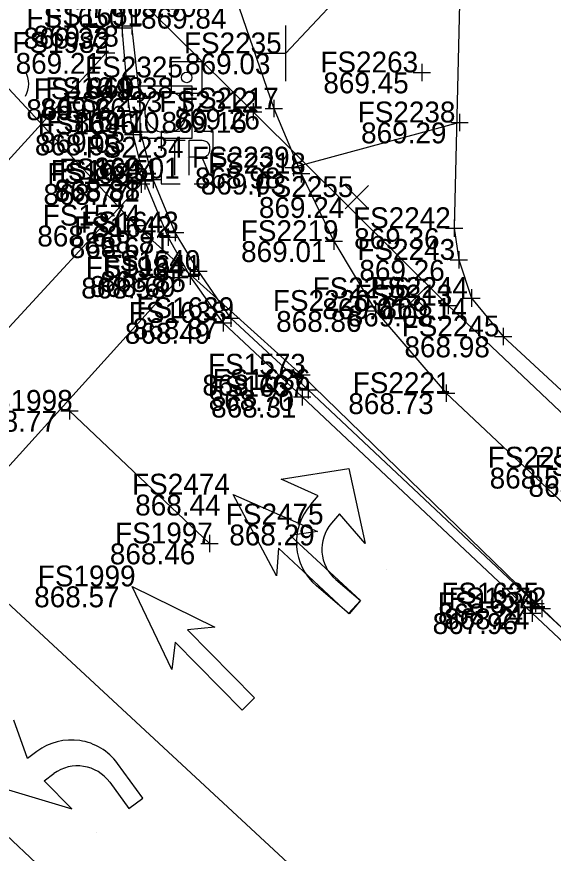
# Model space of a CAD drawing. Extents: x 1479420 to 1479833, y 379731 to 380103.
# Drawn here: x 1479689.07 to 1479719.92, y 379864.1 to 379912.16 of the extents above; entities that cross this region are included whole.
import ezdxf

# ---------------------------------------------------------------- set-up
doc = ezdxf.new("R2010")
doc.units = 0
for name, color, linetype in [('Default', 7, 'Continuous'), ('PM_X_Cells', 7, 'Continuous'), ('PM_X_Channelizing_Line', 7, 'Continuous'), ('PM_X_CL_Double_Solid', 7, 'Continuous'), ('PM_X_Crosswalk', 7, 'Continuous'), ('PM_X_Lane_Line', 7, 'Continuous'), ('PM_X_Stop_Line', 7, 'Continuous'), ('PV_X_Curb', 7, 'Continuous'), ('PV_X_Walk', 7, 'Continuous'), ('SG_X_Poles', 7, 'Continuous'), ('SG_X_PullBox', 7, 'Continuous'), ('SN_X_Public', 7, 'Continuous'), ('SV_X_Random_Point', 7, 'Continuous'), ('SV_X_Shot_Marker', 7, 'Continuous'), ('SV_X_Text_Elevation', 7, 'Continuous'), ('SV_X_Text_Name', 7, 'Continuous'), ('UT_X_Gas', 7, 'Continuous'), ('UT_X_Water', 7, 'Continuous'), ('UT_X_Water_Cells', 7, 'Continuous'), ('VG_X_Flower_Bed', 7, 'Continuous')]:
    doc.layers.add(name, color=color, linetype=linetype)

msp = doc.modelspace()

# ---------------------------------------------------------------- linework, layer by layer
at = {"layer": 'Default'}
msp.add_line((1479704.525, 379910.056), (1479711.29, 379917.236), dxfattribs=at)
at = {"layer": 'PM_X_Cells'}
for p, q in [((1479704.278, 379885.594), (1479708.173, 379886.208)), ((1479708.173, 379886.208), (1479709.112, 379881.892)), ((1479704.278, 379885.594), (1479704.278, 379885.594)), ((1479706.413, 379884.644), (1479704.278, 379885.594)), ((1479701.526, 379884.706), (1479701.526, 379884.706)), ((1479701.526, 379884.706), (1479706.374, 379882.583)), ((1479704.015, 379880.035), (1479701.526, 379884.706)), ((1479705.979, 379884.137), (1479706.413, 379884.644)), ((1479707.628, 379883.603), (1479707.17, 379883.069)), ((1479709.112, 379881.892), (1479707.628, 379883.603)), ((1479706.374, 379882.583), (1479704.801, 379882.355)), ((1479704.801, 379882.355), (1479708.836, 379878.618)), ((1479704.121, 379881.622), (1479704.015, 379880.035)), ((1479708.156, 379877.884), (1479704.121, 379881.622)), ((1479710.354, 379880.39), (1479710.354, 379880.39)), ((1479707.421, 379879.83), (1479708.836, 379878.618)), ((1479695.718, 379879.435), (1479695.718, 379879.435)), ((1479695.718, 379879.435), (1479700.468, 379877.1)), ((1479697.999, 379874.659), (1479695.718, 379879.435)), ((1479708.185, 379877.859), (1479706.303, 379879.471)), ((1479708.836, 379878.618), (1479708.156, 379877.884)), ((1479708.836, 379878.618), (1479708.185, 379877.859)), ((1479708.496, 379878.251), (1479708.496, 379878.251)), ((1479700.468, 379877.1), (1479698.886, 379876.942)), ((1479698.886, 379876.942), (1479702.753, 379873.031)), ((1479698.175, 379876.239), (1479697.999, 379874.659)), ((1479702.042, 379872.328), (1479698.175, 379876.239)), ((1479702.753, 379873.031), (1479702.042, 379872.328)), ((1479702.398, 379872.68), (1479702.398, 379872.68)), ((1479689.698, 379869.557), (1479688.914, 379871.759)), ((1479690.236, 379869.951), (1479689.698, 379869.557)), ((1479696.327, 379867.269), (1479694.864, 379869.27)), ((1479690.643, 379868.266), (1479691.21, 379868.681)), ((1479692.234, 379866.654), (1479690.643, 379868.266)), ((1479694.42, 379868.183), (1479695.52, 379866.679)), ((1479688.004, 379867.922), (1479692.234, 379866.654)), ((1479695.52, 379866.679), (1479696.327, 379867.269)), ((1479693.636, 379865.301), (1479693.636, 379865.301))]:
    msp.add_line(p, q, dxfattribs=at)
for centre, radius, start, end in [((1479708.437, 379881.963), 3.281, 138.5133, 229.4218), ((1479708.915, 379881.575), 2.297, 139.4218, 229.4218), ((1479692.215, 379867.333), 3.281, 36.1769, 127.0854), ((1479692.566, 379866.827), 2.297, 36.1769, 126.1769)]:
    msp.add_arc(centre, radius, start, end, dxfattribs=at)
at = {"layer": 'PM_X_Channelizing_Line'}
msp.add_lwpolyline([(1479685.324, 379881.456), (1479709.405, 379859.144), (1479736.1, 379834.256)], dxfattribs=at)
at = {"layer": 'PM_X_CL_Double_Solid'}
msp.add_lwpolyline([(1479794.219, 379768.772), (1479779.093, 379781.771), (1479763.159, 379795.427), (1479746.619, 379810.624), (1479732.239, 379823.873), (1479714.719, 379840.653), (1479700.713, 379853.615), (1479677.934, 379875.066)], dxfattribs=at)
at = {"layer": 'PM_X_Crosswalk'}
for p, q in [((1479656.672, 379868.951), (1479694.216, 379910.084)), ((1479661.061, 379864.454), (1479696.232, 379902.554))]:
    msp.add_line(p, q, dxfattribs=at)
at = {"layer": 'PM_X_Lane_Line'}
msp.add_line((1479700.154, 379881.903), (1479692.101, 379889.519), dxfattribs=at)
at = {"layer": 'PM_X_Stop_Line'}
msp.add_line((1479698.43, 379897.175), (1479678.605, 379875.296), dxfattribs=at)
at = {"layer": 'PV_X_Curb'}
for points in [[(1479714.573, 379931.716), (1479714.771, 379922.599), (1479714.229, 379900.013), (1479714.491, 379898.192), (1479715.218, 379896.002), (1479717.036, 379893.796), (1479731.944, 379880.013), (1479745.709, 379867.308), (1479763.187, 379850.751), (1479775.061, 379839.578), (1479781.928, 379833.121), (1479783.777, 379830.713), (1479784.214, 379828.705), (1479783.141, 379825.906)], [(1479818.811, 379784.125), (1479817.439, 379785.583), (1479804.233, 379798.167), (1479791.741, 379810.033), (1479778.638, 379821.983), (1479775.464, 379824.819), (1479758.378, 379840.845), (1479740.8, 379857.042), (1479740.592, 379857.626), (1479737.808, 379860.038), (1479735.87, 379861.852), (1479733.787, 379863.763), (1479718.701, 379877.898), (1479705.478, 379890.334), (1479700.95, 379894.575), (1479699.048, 379897.264), (1479697.778, 379899.5), (1479696.445, 379902.732), (1479695.776, 379905.397), (1479695.475, 379907.419), (1479695.142, 379911.53), (1479695.083, 379915.321)], [(1479783.191, 379825.805), (1479782.298, 379824.723), (1479781.461, 379824.102), (1479780.469, 379823.552), (1479779.204, 379823.559), (1479778.041, 379823.771), (1479776.54, 379824.685), (1479775.613, 379825.569), (1479758.651, 379841.237), (1479741.143, 379857.755), (1479738.162, 379860.576), (1479738.292, 379860.892), (1479733.926, 379864.875), (1479733.77, 379864.743), (1479718.903, 379878.446), (1479705.833, 379890.72), (1479701.383, 379894.844), (1479699.526, 379897.551), (1479698.177, 379899.762), (1479696.913, 379902.812), (1479696.188, 379905.546), (1479696.149, 379907.481), (1479695.686, 379911.644), (1479695.62, 379915.117)]]:
    msp.add_lwpolyline(points, dxfattribs=at)
at = {"layer": 'PV_X_Walk'}
msp.add_lwpolyline([(1479714.407, 379931.65), (1479709.589, 379929.394), (1479706.362, 379927.006), (1479703.827, 379924.359), (1479702.38, 379922.179), (1479701.604, 379920.676), (1479701.232, 379918.285), (1479701.216, 379916.698), (1479701.871, 379912.679), (1479703.861, 379906.887), (1479705.425, 379903.147), (1479707.313, 379899.269), (1479709.707, 379895.256), (1479713.76, 379890.533), (1479726.083, 379878.959), (1479737.973, 379867.989), (1479746.242, 379860.487), (1479749.391, 379863.573), (1479751.936, 379861.299), (1479749.037, 379858.043), (1479762.483, 379845.218), (1479775.26, 379833.23), (1479781.252, 379827.717), (1479783.036, 379825.875)], dxfattribs=at)
at = {"layer": 'SG_X_Poles'}
for points in [[(1479697.944, 379907.773), (1479699.744, 379907.773), (1479699.744, 379909.573), (1479697.944, 379909.573)], [(1479696.157, 379905.179), (1479699.157, 379905.179), (1479699.157, 379908.179), (1479696.157, 379908.179)]]:
    msp.add_lwpolyline(points, close=True, dxfattribs=at)
for centre, radius in [((1479698.844, 379908.673), 0.3), ((1479697.657, 379906.679), 1.2)]:
    msp.add_circle(centre, radius, dxfattribs=at)
at = {"layer": 'SG_X_PullBox'}
msp.add_line((1479698.871, 379904.064), (1479698.871, 379904.064), dxfattribs=at)
for points in [[(1479698.471, 379905.564), (1479697.371, 379905.564), (1479697.371, 379904.464)], [(1479700.371, 379904.464), (1479700.371, 379905.564), (1479699.271, 379905.564)], [(1479697.515, 379905.064), (1479698.759, 379905.064)], [(1479698.145, 379905.064), (1479698.145, 379903.064)], [(1479698.983, 379903.064), (1479698.983, 379905.064), (1479699.739, 379905.064), (1479699.817, 379905.048), (1479699.928, 379905.016), (1479699.975, 379904.985), (1479700.022, 379904.953), (1479700.085, 379904.874), (1479700.132, 379904.796), (1479700.164, 379904.67), (1479700.164, 379904.481), (1479700.148, 379904.418), (1479700.117, 379904.323), (1479700.054, 379904.213), (1479699.991, 379904.166), (1479699.943, 379904.134), (1479699.912, 379904.118), (1479699.865, 379904.103), (1479699.723, 379904.087), (1479698.983, 379904.087)], [(1479699.723, 379904.087), (1479700.164, 379903.064)], [(1479697.371, 379903.664), (1479697.371, 379902.564), (1479698.471, 379902.564)], [(1479699.271, 379902.564), (1479700.371, 379902.564), (1479700.371, 379903.664)]]:
    msp.add_lwpolyline(points, dxfattribs=at)
at = {"layer": 'SN_X_Public'}
for p, q in [((1479704.525, 379911.656), (1479704.525, 379908.456)), ((1479704.525, 379910.056), (1479702.925, 379910.056))]:
    msp.add_line(p, q, dxfattribs=at)
at = {"layer": 'SV_X_Random_Point'}
for p, q in [((1479707.962, 379901.133), (1479709.296, 379902.468)), ((1479707.962, 379902.468), (1479709.296, 379901.133)), ((1479711.313, 379895.319), (1479712.647, 379896.654)), ((1479711.313, 379896.654), (1479712.647, 379895.319))]:
    msp.add_line(p, q, dxfattribs=at)
at = {"layer": 'SV_X_Shot_Marker'}
for p, q in [((1479695.142, 379912.03), (1479695.142, 379911.03)), ((1479695.686, 379912.144), (1479695.686, 379911.144)), ((1479694.642, 379911.53), (1479695.642, 379911.53)), ((1479695.142, 379911.53), (1479695.142, 379911.53)), ((1479695.186, 379911.644), (1479696.186, 379911.644)), ((1479695.686, 379911.644), (1479695.686, 379911.644)), ((1479694.216, 379910.584), (1479694.216, 379909.584)), ((1479693.716, 379910.084), (1479694.716, 379910.084)), ((1479694.216, 379910.084), (1479694.216, 379910.084)), ((1479712.371, 379909.461), (1479712.371, 379908.461)), ((1479711.871, 379908.961), (1479712.871, 379908.961)), ((1479712.371, 379908.961), (1479712.371, 379908.961)), ((1479695.475, 379907.919), (1479695.475, 379906.919)), ((1479696.149, 379907.981), (1479696.149, 379906.981)), ((1479694.975, 379907.419), (1479695.975, 379907.419)), ((1479695.475, 379907.419), (1479695.475, 379907.419)), ((1479695.649, 379907.481), (1479696.649, 379907.481)), ((1479696.149, 379907.481), (1479696.149, 379907.481)), ((1479702.659, 379907.194), (1479702.659, 379906.194)), ((1479703.861, 379907.387), (1479703.861, 379906.387)), ((1479702.159, 379906.694), (1479703.159, 379906.694)), ((1479702.659, 379906.694), (1479702.659, 379906.694)), ((1479703.361, 379906.887), (1479704.361, 379906.887)), ((1479703.861, 379906.887), (1479703.861, 379906.887)), ((1479714.524, 379906.587), (1479714.524, 379905.587)), ((1479696.188, 379906.046), (1479696.188, 379905.046)), ((1479714.024, 379906.087), (1479715.024, 379906.087)), ((1479714.524, 379906.087), (1479714.524, 379906.087)), ((1479695.688, 379905.546), (1479696.688, 379905.546)), ((1479695.776, 379905.897), (1479695.776, 379904.897)), ((1479696.188, 379905.546), (1479696.188, 379905.546)), ((1479695.276, 379905.397), (1479696.276, 379905.397)), ((1479695.776, 379905.397), (1479695.776, 379905.397)), ((1479704.993, 379903.996), (1479704.993, 379902.996)), ((1479705.425, 379903.647), (1479705.425, 379902.647)), ((1479696.445, 379903.232), (1479696.445, 379902.232)), ((1479696.913, 379903.312), (1479696.913, 379902.312)), ((1479704.493, 379903.496), (1479705.493, 379903.496)), ((1479704.925, 379903.147), (1479705.925, 379903.147)), ((1479704.993, 379903.496), (1479704.993, 379903.496)), ((1479705.425, 379903.147), (1479705.425, 379903.147)), ((1479695.945, 379902.732), (1479696.945, 379902.732)), ((1479696.232, 379903.054), (1479696.232, 379902.054)), ((1479696.413, 379902.812), (1479697.413, 379902.812)), ((1479696.445, 379902.732), (1479696.445, 379902.732)), ((1479696.913, 379902.812), (1479696.913, 379902.812)), ((1479695.732, 379902.554), (1479696.732, 379902.554)), ((1479696.232, 379902.554), (1479696.232, 379902.554)), ((1479695.924, 379900.661), (1479695.924, 379899.661)), ((1479698.177, 379900.262), (1479698.177, 379899.262)), ((1479714.229, 379900.513), (1479714.229, 379899.513)), ((1479695.424, 379900.161), (1479696.424, 379900.161)), ((1479695.924, 379900.161), (1479695.924, 379900.161)), ((1479697.677, 379899.762), (1479698.677, 379899.762)), ((1479697.778, 379900), (1479697.778, 379899)), ((1479698.177, 379899.762), (1479698.177, 379899.762)), ((1479707.313, 379899.769), (1479707.313, 379898.769)), ((1479713.729, 379900.013), (1479714.729, 379900.013)), ((1479714.229, 379900.013), (1479714.229, 379900.013)), ((1479697.278, 379899.5), (1479698.278, 379899.5)), ((1479697.778, 379899.5), (1479697.778, 379899.5)), ((1479706.813, 379899.269), (1479707.813, 379899.269)), ((1479707.313, 379899.269), (1479707.313, 379899.269)), ((1479714.491, 379898.692), (1479714.491, 379897.692)), ((1479699.526, 379898.051), (1479699.526, 379897.051)), ((1479713.991, 379898.192), (1479714.991, 379898.192)), ((1479714.491, 379898.192), (1479714.491, 379898.192)), ((1479698.43, 379897.675), (1479698.43, 379896.675)), ((1479699.026, 379897.551), (1479700.026, 379897.551)), ((1479699.048, 379897.764), (1479699.048, 379896.764)), ((1479699.526, 379897.551), (1479699.526, 379897.551)), ((1479697.93, 379897.175), (1479698.93, 379897.175)), ((1479698.43, 379897.175), (1479698.43, 379897.175)), ((1479698.548, 379897.264), (1479699.548, 379897.264)), ((1479699.048, 379897.264), (1479699.048, 379897.264)), ((1479715.218, 379896.502), (1479715.218, 379895.502)), ((1479713.881, 379896.067), (1479713.881, 379895.067)), ((1479714.718, 379896.002), (1479715.718, 379896.002)), ((1479715.218, 379896.002), (1479715.218, 379896.002)), ((1479709.707, 379895.756), (1479709.707, 379894.756)), ((1479713.381, 379895.567), (1479714.381, 379895.567)), ((1479713.881, 379895.567), (1479713.881, 379895.567)), ((1479700.95, 379895.075), (1479700.95, 379894.075)), ((1479701.383, 379895.344), (1479701.383, 379894.344)), ((1479709.207, 379895.256), (1479710.207, 379895.256)), ((1479709.707, 379895.256), (1479709.707, 379895.256)), ((1479700.45, 379894.575), (1479701.45, 379894.575)), ((1479700.883, 379894.844), (1479701.883, 379894.844)), ((1479700.95, 379894.575), (1479700.95, 379894.575)), ((1479701.383, 379894.844), (1479701.383, 379894.844)), ((1479717.036, 379894.296), (1479717.036, 379893.296)), ((1479716.536, 379893.796), (1479717.536, 379893.796)), ((1479717.036, 379893.796), (1479717.036, 379893.796)), ((1479705.441, 379892.096), (1479705.441, 379891.096)), ((1479704.941, 379891.596), (1479705.941, 379891.596)), ((1479705.441, 379891.596), (1479705.441, 379891.596)), ((1479705.833, 379891.22), (1479705.833, 379890.22)), ((1479705.333, 379890.72), (1479706.333, 379890.72)), ((1479705.478, 379890.834), (1479705.478, 379889.834)), ((1479705.833, 379890.72), (1479705.833, 379890.72)), ((1479713.76, 379891.033), (1479713.76, 379890.033)), ((1479704.978, 379890.334), (1479705.978, 379890.334)), ((1479705.478, 379890.334), (1479705.478, 379890.334)), ((1479713.26, 379890.533), (1479714.26, 379890.533)), ((1479713.76, 379890.533), (1479713.76, 379890.533)), ((1479692.101, 379890.019), (1479692.101, 379889.019)), ((1479691.601, 379889.519), (1479692.601, 379889.519)), ((1479692.101, 379889.519), (1479692.101, 379889.519)), ((1479700.154, 379882.403), (1479700.154, 379881.403)), ((1479699.654, 379881.903), (1479700.654, 379881.903)), ((1479700.154, 379881.903), (1479700.154, 379881.903)), ((1479718.903, 379878.946), (1479718.903, 379877.946)), ((1479719.261, 379878.671), (1479719.261, 379877.671)), ((1479718.403, 379878.446), (1479719.403, 379878.446)), ((1479718.701, 379878.398), (1479718.701, 379877.398)), ((1479718.761, 379878.171), (1479719.761, 379878.171)), ((1479718.903, 379878.446), (1479718.903, 379878.446)), ((1479719.261, 379878.171), (1479719.261, 379878.171)), ((1479718.201, 379877.898), (1479719.201, 379877.898)), ((1479718.701, 379877.898), (1479718.701, 379877.898))]:
    msp.add_line(p, q, dxfattribs=at)
at = {"layer": 'UT_X_Gas'}
msp.add_lwpolyline([(1479667.444, 379946.572), (1479666.862, 379942.802), (1479667.538, 379940.507), (1479675.403, 379934.504), (1479682.743, 379926.326), (1479692.421, 379916.824), (1479702.659, 379906.694), (1479713.881, 379895.567), (1479724.225, 379885.781), (1479733.117, 379877.795), (1479742.697, 379869.326), (1479754.816, 379857.131), (1479762.869, 379849.318), (1479772.436, 379840.641), (1479780.346, 379832.715), (1479784.901, 379828.191), (1479795.906, 379818.324), (1479806.128, 379806.719), (1479816.671, 379794.927)], dxfattribs=at)
at = {"layer": 'UT_X_Water'}
msp.add_lwpolyline([(1479682.752, 379913.809), (1479688.353, 379908.314), (1479695.924, 379900.161), (1479705.441, 379891.596), (1479719.261, 379878.171), (1479726.79, 379870.913), (1479729.608, 379870.544), (1479735.551, 379869.684), (1479739.947, 379866.49), (1479744.65, 379861.847), (1479745.833, 379856.023), (1479753.929, 379847.124), (1479764.701, 379835.97), (1479779.815, 379822.167), (1479798.248, 379804.283), (1479815.468, 379787.444)], dxfattribs=at)
at = {"layer": 'UT_X_Water_Cells'}
msp.add_arc((1479688.366, 379908.302), 1.4, 330.0184, 29.9816, dxfattribs=at)
at = {"layer": 'VG_X_Flower_Bed'}
msp.add_line((1479714.524, 379906.087), (1479704.993, 379903.496), dxfattribs=at)

# ---------------------------------------------------------------- texts
at = {"layer": 'SV_X_Text_Elevation'}
for s, p in [('869.90', (1479694.5, 379912.147)), ('869.84', (1479696.221, 379911.479)), ('869.33', (1479689.464, 379910.33)), ('869.78', (1479690.036, 379910.444)), ('869.21', (1479689.009, 379908.884)), ('869.03', (1479698.752, 379908.856)), ('869.45', (1479706.702, 379907.761)), ('869.38', (1479693.156, 379907.473)), ('869.06', (1479689.627, 379906.219)), ('869.26', (1479690.433, 379906.281)), ('869.10', (1479692.367, 379905.479)), ('869.16', (1479697.397, 379905.494)), ('869.26', (1479698.145, 379905.687)), ('869.29', (1479708.874, 379904.887)), ('869.03', (1479690.415, 379904.346)), ('868.95', (1479690.117, 379904.197)), ('869.01', (1479693.532, 379902.864)), ('868.98', (1479699.324, 379902.296)), ('869.03', (1479699.652, 379901.947)), ('868.81', (1479691.238, 379901.532)), ('868.88', (1479691.263, 379901.612)), ('868.77', (1479690.61, 379901.354)), ('869.24', (1479702.998, 379900.601)), ('868.68', (1479690.255, 379898.961)), ('868.81', (1479692.97, 379898.562)), ('869.36', (1479708.475, 379898.813)), ('868.67', (1479692.119, 379898.3)), ('869.01', (1479701.974, 379898.069)), ('869.26', (1479708.775, 379896.992)), ('868.85', (1479693.885, 379896.351)), ('868.58', (1479692.78, 379895.975)), ('868.60', (1479693.285, 379896.064)), ('869.01', (1479706.641, 379894.786)), ('869.14', (1479710.041, 379894.802)), ('869.08', (1479708.099, 379894.367)), ('868.86', (1479703.991, 379894.056)), ('868.49', (1479695.291, 379893.375)), ('868.87', (1479695.742, 379893.644)), ('868.98', (1479711.367, 379892.596)), ('868.76', (1479699.744, 379890.396)), ('868.70', (1479700.107, 379889.52)), ('868.31', (1479700.252, 379889.134)), ('868.73', (1479708.138, 379889.333)), ('868.77', (1479686.479, 379888.319)), ('868.56', (1479716.266, 379885.055)), ('868.46', (1479718.5, 379884.581)), ('868.44', (1479695.885, 379883.506)), ('868.29', (1479701.294, 379881.789)), ('868.46', (1479694.429, 379880.703)), ('868.57', (1479690.077, 379878.235)), ('868.24', (1479713.291, 379877.246)), ('868.24', (1479713.649, 379876.971)), ('867.96', (1479712.985, 379876.698))]:
    msp.add_text(s, height=1.2, dxfattribs=at).set_placement(p)
at = {"layer": 'SV_X_Text_Name'}
for s, p in [('FS1650', (1479689.634, 379911.53)), ('FS1651', (1479690.716, 379911.644)), ('FS1982', (1479688.822, 379910.084)), ('FS2235', (1479698.686, 379910.056)), ('FS2325', (1479693.005, 379908.673)), ('FS2263', (1479706.532, 379908.961)), ('FS1649', (1479690.052, 379907.419)), ('FS1648', (1479690.726, 379907.481)), ('FS2233', (1479691.818, 379906.679)), ('FS2312', (1479697.284, 379906.694)), ('FS2217', (1479698.514, 379906.887)), ('FS2238', (1479708.676, 379906.087)), ('FS1646', (1479690.287, 379905.397)), ('FS1647', (1479690.775, 379905.546)), ('FS2234', (1479693.042, 379904.064)), ('FS2239', (1479699.145, 379903.496)), ('FS2218', (1479700.069, 379903.147)), ('FS1983', (1479690.828, 379902.554)), ('FS1645', (1479691.032, 379902.732)), ('FS1644', (1479691.509, 379902.812)), ('FS2255', (1479702.809, 379901.801)), ('FS1574', (1479690.568, 379900.161)), ('FS2242', (1479708.409, 379900.013)), ('FS1642', (1479692.374, 379899.5)), ('FS1643', (1479692.764, 379899.762)), ('FS2219', (1479701.957, 379899.269)), ('FS2243', (1479708.662, 379898.192)), ('FS1640', (1479694.009, 379897.551)), ('FS1984', (1479693.036, 379897.175)), ('FS1641', (1479694.069, 379897.264)), ('FS2256', (1479706.084, 379895.986)), ('FS2244', (1479709.398, 379896.002)), ('FS2220', (1479703.802, 379895.256)), ('FS2313', (1479708.496, 379895.567)), ('FS1639', (1479695.951, 379894.844)), ('FS1638', (1479695.518, 379894.575)), ('FS2245', (1479711.207, 379893.796)), ('FS1573', (1479700.075, 379891.596)), ('FS1637', (1479700.055, 379890.334)), ('FS1636', (1479700.335, 379890.72)), ('FS2221', (1479708.393, 379890.533)), ('FS1998', (1479686.669, 379889.519)), ('FS2257', (1479716.162, 379886.255)), ('FS2314', (1479718.85, 379885.781)), ('FS2474', (1479695.706, 379884.706)), ('FS2475', (1479701.096, 379882.989)), ('FS1997', (1479694.731, 379881.903)), ('FS1999', (1479690.286, 379879.435)), ('FS1635', (1479713.48, 379878.446)), ('FS1634', (1479713.288, 379877.898)), ('FS1572', (1479713.905, 379878.171))]:
    msp.add_text(s, height=1.2, dxfattribs=at).set_placement(p)

doc.saveas('drawing.dxf')
